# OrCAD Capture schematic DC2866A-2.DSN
size Custom
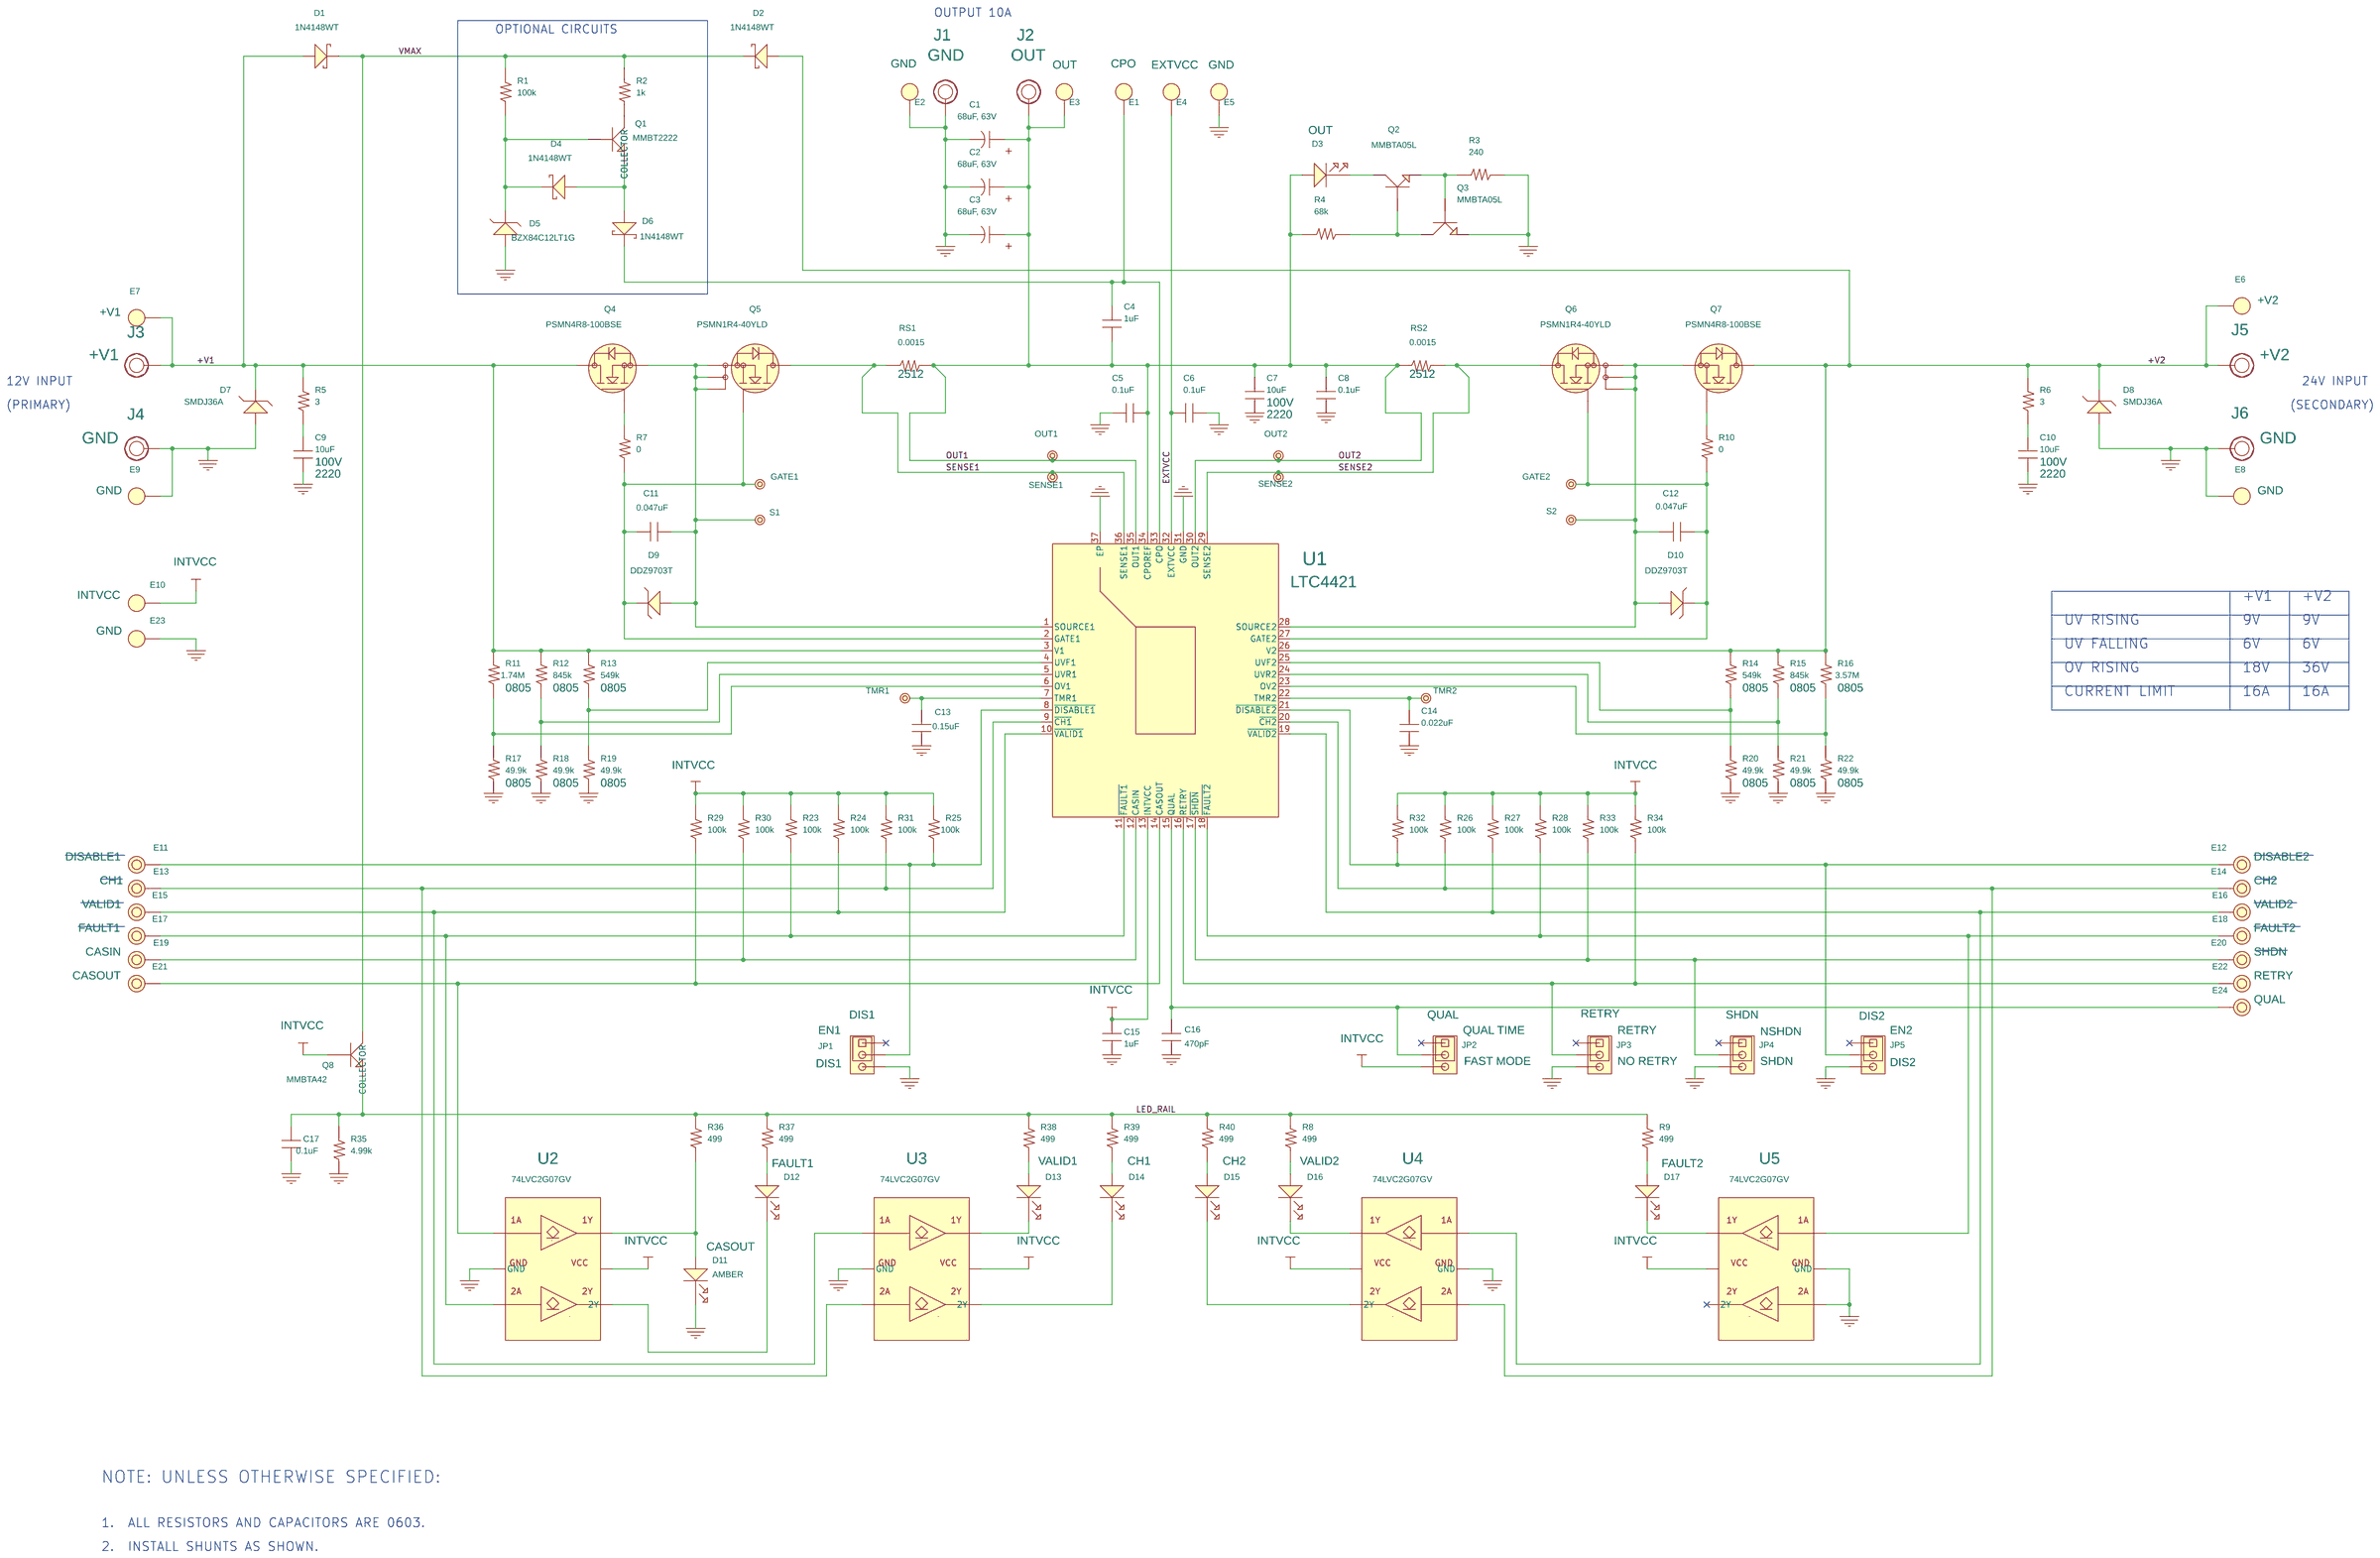
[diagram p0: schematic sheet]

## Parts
C1  68uF, 63V  [C-PANA-F-8X10.2]
C2  68uF, 63V  [C-PANA-F-8X10.2]
C3  68uF, 63V  [C-PANA-F-8X10.2]
C4  1uF  [0603]
C5  0.1uF  [0603]
C6  0.1uF  [0603]
C7  10uF  [2220]
C8  0.1uF  [0603]
C9  10uF  [2220]
C10  10uF  [2220]
C11  0.047uF  [0603]
C12  0.047uF  [0603]
C13  0.15uF  [0603]
C14  0.022uF  [0603]
C15  1uF  [0603]
C16  470pF  [0603]
C17  0.1uF  [0603]
D1  1N4148WT  [SOD523]
D2  1N4148WT  [SOD523]
D3  WE, 150141VS73100  [LED-WE-150141]
D4  1N4148WT  [SOD523]
D5  BZX84C12LT1G  [SOT23]
D6  1N4148WT  [SOD523]
D7  SMDJ36A  [SMC-DIODE]
D8  SMDJ36A  [SMC-DIODE]
D9  DDZ9703T  [SOD523]
D10  DDZ9703T  [SOD523]
D11  WE, 150141AS73100  [LED-WE-150141]
D12  WE, 150141RS73100  [LED-WE-150141]
D13  WE, 150141VS73100  [LED-WE-150141]
D14  WE, 150141VS73100  [LED-WE-150141]
D15  WE, 150141VS73100  [LED-WE-150141]
D16  WE, 150141VS73100  [LED-WE-150141]
D17  WE, 150141RS73100  [LED-WE-150141]
E1  MIL-MAX-2501  [MILL-MAX-2501]
E2  MIL-MAX-2501  [MILL-MAX-2501]
E3  MIL-MAX-2501  [MILL-MAX-2501]
E4  MIL-MAX-2501  [MILL-MAX-2501]
E5  MIL-MAX-2501  [MILL-MAX-2501]
E6  MIL-MAX-2501  [MILL-MAX-2501]
E7  MIL-MAX-2501  [MILL-MAX-2501]
E8  MIL-MAX-2501  [MILL-MAX-2501]
E9  MIL-MAX-2501  [MILL-MAX-2501]
E10  MIL-MAX-2501  [MILL-MAX-2501]
E11  MIL-MAX-2308  [MILL-MAX-2308]
E12  MIL-MAX-2308  [MILL-MAX-2308]
E13  MIL-MAX-2308  [MILL-MAX-2308]
E14  MIL-MAX-2308  [MILL-MAX-2308]
E15  MIL-MAX-2308  [MILL-MAX-2308]
E16  MIL-MAX-2308  [MILL-MAX-2308]
E17  MIL-MAX-2308  [MILL-MAX-2308]
E18  MIL-MAX-2308  [MILL-MAX-2308]
E19  MIL-MAX-2308  [MILL-MAX-2308]
E20  MIL-MAX-2308  [MILL-MAX-2308]
E21  MIL-MAX-2308  [MILL-MAX-2308]
E22  MIL-MAX-2308  [MILL-MAX-2308]
E23  MIL-MAX-2501  [MILL-MAX-2501]
E24  MIL-MAX-2308  [MILL-MAX-2308]
GATE1  E-060-035  [PAD060-035]
GATE2  E-060-035  [PAD060-035]
J1  Banana Jack  [KEY-575]
J2  Banana Jack  [KEY-575]
J3  Banana Jack  [KEY-575]
J4  Banana Jack  [KEY-575]
J5  Banana Jack  [KEY-575]
J6  Banana Jack  [KEY-575]
JP1  HD1X3-079  [HD1X3-079]
JP2  HD1X3-079  [HD1X3-079]
JP3  HD1X3-079  [HD1X3-079]
JP4  HD1X3-079  [HD1X3-079]
JP5  HD1X3-079  [HD1X3-079]
OUT1  E-060-035  [PAD060-035]
OUT2  E-060-035  [PAD060-035]
Q1  MMBT2222  [SOT23]
Q2  MMBTA05L  [SOT23]
Q3  MMBTA05L  [SOT23]
Q4  PSMN4R8-100BSE  [D2PAK]
Q5  PSMN1R4-40YLD  [LFPAK56]
Q6  PSMN1R4-40YLD  [LFPAK56]
Q7  PSMN4R8-100BSE  [D2PAK]
Q8  MMBTA42  [SOT23]
R1  100k  [0603]
R2  1k  [0603]
R3  240  [0603]
R4  68k  [0603]
R5  3  [0603]
R6  3  [0603]
R7  0  [0603]
R8  499  [0603]
R9  499  [0603]
R10  0  [0603]
R11  1.74M  [0805]
R12  845k  [0805]
R13  549k  [0805]
R14  549k  [0805]
R15  845k  [0805]
R16  3.57M  [0805]
R17  49.9k  [0805]
R18  49.9k  [0805]
R19  49.9k  [0805]
R20  49.9k  [0805]
R21  49.9k  [0805]
R22  49.9k  [0805]
R23  100k  [0603]
R24  100k  [0603]
R25  100k  [0603]
R26  100k  [0603]
R27  100k  [0603]
R28  100k  [0603]
R29  100k  [0603]
R30  100k  [0603]
R31  100k  [0603]
R32  100k  [0603]
R33  100k  [0603]
R34  100k  [0603]
R35  4.99k  [0603]
R36  499  [0603]
R37  499  [0603]
R38  499  [0603]
R39  499  [0603]
R40  499  [0603]
RS1  0.0015  [2512]
RS2  0.0015  [2512]
S1  E-060-035  [PAD060-035]
S2  E-060-035  [PAD060-035]
SENSE1  E-060-035  [PAD060-035]
SENSE2  E-060-035  [PAD060-035]
TMR1  E-060-035  [PAD060-035]
TMR2  E-060-035  [PAD060-035]
U1  LTC4421  [QFN36UHE-5X6]
U2  74LVC2G07GV  [TSOP6]
U3  74LVC2G07GV  [TSOP6]
U4  74LVC2G07GV  [TSOP6]
U5  74LVC2G07GV  [TSOP6]

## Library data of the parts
C1-C3 = CAP
C4-C6 C8 C15 C17 = CAP-NP
C7 C9 C10 = CAP-NP: VOLTAGE: 100V
C11-C14 C16 = CAP-NP: VOLTAGE: 25V
D1 D2 = DIODE-1N4148WT-SOD523
D3 = LED-WE-150141VS73100-GREEN: 1ST PART FIELD: OUT
D4 D6 = DIODE-1N4148WT-SOD523: OPT: OPT
D5 = DIODE-BZX84CXXXLT1G-SOT23: OPT: OPT
D7 D8 = DIODE-5.0SMDJ-SMC-DIODE
D9 D10 = DIODE-DDZ9703T-SOD523
D11 = LED-WE-150141RS73100-RED: 1ST PART FIELD: CASOUT; LED: AMBER
D12 = LED-WE-150141RS73100-RED: 1ST PART FIELD: FAULT1
D13 = LED-WE-150141VS73100-GREEN: 1ST PART FIELD: VALID1
D14 = LED-WE-150141VS73100-GREEN: 1ST PART FIELD: CH1
D15 = LED-WE-150141VS73100-GREEN: 1ST PART FIELD: CH2
D16 = LED-WE-150141VS73100-GREEN: 1ST PART FIELD: VALID2
D17 = LED-WE-150141RS73100-RED: 1ST PART FIELD: FAULT2
E1 = E-094: 1ST PART FIELD: CPO
E2 E5 E8 E9 E23 = E-094: 1ST PART FIELD: GND
E3 = E-094: 1ST PART FIELD: OUT
E4 = E-094: 1ST PART FIELD: EXTVCC
E6 = E-094: 1ST PART FIELD: +V2
E7 = E-094: 1ST PART FIELD: +V1
E10 = E-094: 1ST PART FIELD: INTVCC
E11 = E-064: 1ST PART FIELD: DISABLE1
E12 = E-064: 1ST PART FIELD: DISABLE2
E13 = E-064: 1ST PART FIELD: CH1
E14 = E-064: 1ST PART FIELD: CH2
E15 = E-064: 1ST PART FIELD: VALID1
E16 = E-064: 1ST PART FIELD: VALID2
E17 = E-064: 1ST PART FIELD: FAULT1
E18 = E-064: 1ST PART FIELD: FAULT2
E19 = E-064: 1ST PART FIELD: CASIN
E20 = E-064: 1ST PART FIELD: SHDN
E21 = E-064: 1ST PART FIELD: CASOUT
E22 = E-064: 1ST PART FIELD: RETRY
E24 = E-064: 1ST PART FIELD: QUAL
GATE1 GATE2 OUT1 OUT2 S1 S2 SENSE1 SENSE2 TMR1 TMR2 = E-060-035
J1 J4 J6 = E-KEY-575: FUNTION: GND
J2 = E-KEY-575: FUNTION: OUT
J3 = E-KEY-575: FUNTION: +V1
J5 = E-KEY-575: FUNTION: +V2
JP1 = HD1X3: 1ST PART FIELD: DIS1; 2ND PART FIELD: EN1; 3RD PART FIELD: DIS1
JP2 = HD1X3: 1ST PART FIELD: QUAL TIME; 2ND PART FIELD: FAST MODE; 3RD PART FIELD: QUAL
JP3 = HD1X3: 1ST PART FIELD: NO RETRY; 2ND PART FIELD: RETRY; 3RD PART FIELD: RETRY
JP4 = HD1X3: 1ST PART FIELD: SHDN; 2ND PART FIELD: NSHDN; 3RD PART FIELD: SHDN
JP5 = HD1X3: 1ST PART FIELD: DIS2; 2ND PART FIELD: EN2; 3RD PART FIELD: DIS2
Q1 = NPN-MMBT2222A-SOT23: OPT: OPT
Q2 Q3 = NPN-MMBTA05L-SOT23
Q4 Q7 = MOSFET_N-DIODE-PSMN4R8-D2PAK
Q5 Q6 = MOSFET_N-DIODE-PSMN1R4-LFPAK56
Q8 = MMBTA42-SOT23
R1 R2 = R: OPT: OPT
R3-R40 RS1 RS2 = R
U1 = LTC4421IUHE-QFN36UHE-5X6
U2-U5 = 74LVC2G07GV-TSOP6

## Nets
+V1: D1.2 D7.1 E7.1(A) J3.1 Q4.2 R5.2 R11.2 R12.2 R13.2 U1.3(V1)
+V2: D2.2 D8.1 E6.1(A) J5.1 Q7.2 R6.2 R14.2 R15.2 R16.2 U1.26(V2)
AGND: C1.2 C2.2 C3.2 C5.1 C6.1 C7.2 C8.2 C9.2 C10.2 C13.1 C14.1 C15.2 C16.1 C17.2 D5.1 D7.2 D8.2 D11.1 E2.1(A) E5.1(A) E8.1(A) E9.1(A) E23.1(A) J1.1 J4.1 J6.1 JP1.3 JP3.3 JP4.3 JP5.3 Q3.2 R3.1 R17.1 R18.1 R19.1 R20.1 R21.1 R22.1 R35.1 U1.31(GND) U1.37(EP) U2.2(GND) U3.2(GND) U4.2(GND) U5.2(GND) U5.3
EXTVCC: C6.2 E4.1(A) U1.32(EXTVCC)
INTVCC: C15.1 E10.1(A) JP2.3 Q8.1 R23.2 R24.2 R25.2 R26.2 R27.2 R28.2 R29.2 R30.2 R31.2 R32.2 R33.2 R34.2 U1.13(INTVCC) U2.5 U3.5 U4.5 U5.5
LED_RAIL: C17.1 Q8.2 R8.2 R9.2 R35.2 R36.2 R37.2 R38.2 R39.2 R40.2
OUT1: C1.1 C2.1 C3.1 C4.2 C5.2 C7.1 C8.1 D3.2 E3.1(A) J2.1 OUT1.1 OUT2.1 R4.2 RS1.2 RS2.1 U1.30(OUT2) U1.34(CPOREF) U1.35(OUT1)
SENSE1: Q5.5 RS1.1 SENSE1.1 U1.36(SENSE1)
SENSE2: Q6.5 RS2.2 SENSE2.1 U1.29(SENSE2)
VMAX: D1.1 D2.1 Q8.3(COLLECTOR) R1.2 R2.2
N21822463: Q7.1 R10.2
N21822471: C12.1 D10.2 Q6.1 Q6.2 Q6.3 Q7.3 S2.1 U1.28(SOURCE2)
N21822619: C12.2 D10.1 GATE2.1 Q6.4 R10.1 U1.27(GATE2)
N21822657: C10.1 R6.1
N21823472: E20.1(A) JP4.2 R33.1 U1.17(~{SHDN})
N21823608: E22.1(A) JP3.2 R34.1 U1.16(RETRY)
N21823617: C16.2 E24.1(A) JP2.2 U1.15(QUAL)
N21823866: E12.1(A) JP5.2 R32.1 U1.21(~{DISABLE2})
N21827044: R14.1 R20.2 U1.25(UVF2)
N21827047: R15.1 R21.2 U1.24(UVR2)
N21827050: R16.1 R22.2 U1.23(OV2)
N21827270: C14.2 TMR2.1 U1.22(TMR2)
N21827852: E18.1(A) R28.1 U1.18(~{FAULT2}) U5.1
N21827857: E16.1(A) R27.1 U1.19(~{VALID2}) U4.1
N21827866: E14.1(A) R26.1 U1.20(~{CH2}) U4.3
N21830259: D11.2 R36.1 U2.6
N21831585: D12.2 R37.1
N21831593: D12.1 U2.4(2Y)
N21831815: D13.2 R38.1
N21831848: D14.2 R39.1
N21831850: D13.1 U3.6
N21831852: D14.1 U3.4(2Y)
N21831924: E21.1(A) R29.1 U1.14(CASOUT) U2.1
N21831931: E17.1(A) R23.1 U1.11(~{FAULT1}) U2.3
N21831938: E15.1(A) R24.1 U1.10(~{VALID1}) U3.1
N21831956: E13.1(A) R31.1 U1.9(~{CH1}) U3.3
N21832313: D17.2 R9.1
N21832348: D17.1 U5.6
N21832378: D16.2 R8.1
N21832411: D15.2 R40.1
N21832413: D16.1 U4.6
N21832415: D15.1 U4.4(2Y)
N21836367: C11.2 D9.2 Q4.3 Q5.1 Q5.2 Q5.3 S1.1 U1.1(SOURCE1)
N21836371: C11.1 D9.1 GATE1.1 Q5.4 R7.1 U1.2(GATE1)
N21836452: Q4.1 R7.2
N21836508: C9.1 R5.1
N21838193: R13.1 R19.2 U1.4(UVF1)
N21838195: R12.1 R18.2 U1.5(UVR1)
N21838197: R11.1 R17.2 U1.6(OV1)
N21838240: C13.2 TMR1.1 U1.7(TMR1)
N21838264: E11.1(A) JP1.2 R25.1 U1.8(~{DISABLE1})
N21839857: E19.1(A) R30.1 U1.12(CASIN)
N21852049: C4.1 D6.1 E1.1(A) U1.33(CPO)
N21852307: D4.2 D6.2 Q1.2
N21852348: D4.1 D5.3 Q1.1 R1.1
N21860043: D3.1 Q2.3
N21860049: Q2.1 Q3.3 R4.1
N21860139: Q2.2 Q3.1 R3.2
N21889612: Q1.3(COLLECTOR) R2.1

Not connected (* = marked no-connect by the designer): JP1 1*; JP2 1*; JP3 1*; JP4 1*; JP5 1*; U5 4(2Y)*

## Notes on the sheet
- OUTPUT 10A
- OPTIONAL CIRCUITS
- 12V INPUT
- 24V INPUT
- (PRIMARY)
- (SECONDARY)
- +V1
- +V2
- UV RISING
- 9V
- 9V
- UV FALLING
- 6V
- 6V
- OV RISING
- 18V
- 36V
- CURRENT LIMIT
- 16A
- 16A
- NOTE: UNLESS OTHERWISE SPECIFIED:
- 1.  ALL RESISTORS AND CAPACITORS ARE 0603.
- 2.  INSTALL SHUNTS AS SHOWN.
